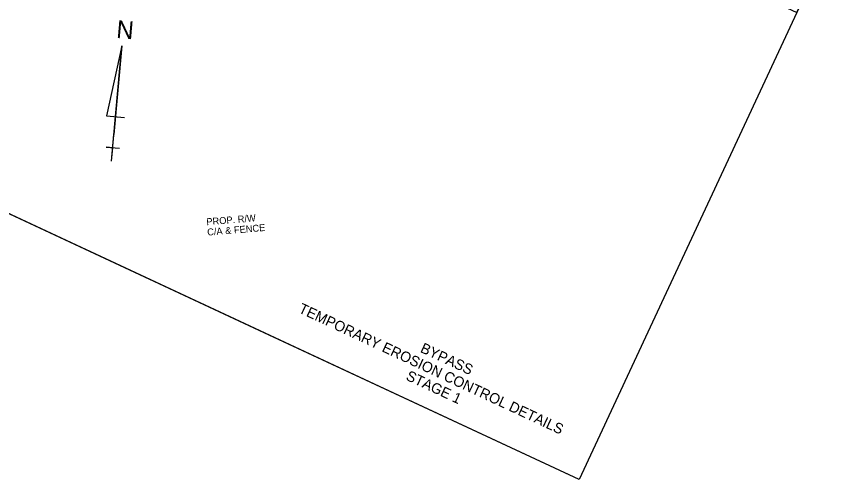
# Model space of a CAD drawing. Extents: x 980231 to 982096, y 1837566 to 1839185.
# Drawn here: x 981190 to 981897, y 1837566 to 1837967 of the extents above; entities that cross this region are included whole.
import ezdxf

# ---------------------------------------------------------------- set-up
doc = ezdxf.new("R2010")
doc.units = 0
for name, color, linetype in [('60', 7, 'Continuous'), ('63', 7, 'Continuous'), ('G-Border-Sheet', 7, 'Continuous'), ('R_Draft', 7, 'Continuous')]:
    doc.layers.add(name, color=color, linetype=linetype)

msp = doc.modelspace()

# ---------------------------------------------------------------- linework, layer by layer
at = {"layer": '63'}
for p, q in [((981281.06, 1837941.12), (981268.03, 1837880.49)), ((981272.34, 1837841.5), (981281.06, 1837941.12)), ((981281.06, 1837941.12), (981274.35, 1837864.49)), ((981268.03, 1837880.49), (981283.36, 1837879.15)), ((981272.34, 1837841.5), (981274.35, 1837864.49)), ((981273.35, 1837853), (981267.6, 1837853.5)), ((981267.6, 1837853.5), (981279.09, 1837852.49)), ((981272.34, 1837841.5), (981273.35, 1837853))]:
    msp.add_line(p, q, dxfattribs=at)
at = {"layer": 'G-Border-Sheet'}
for points in [[(981897.02, 1838038.3), (981676.77, 1837565.97), (981495.51, 1837650.49), (980230.88, 1838240.2), (980451.13, 1838712.53), (980461.01, 1838707.92), (980430.47, 1838642.44), (980815.65, 1838462.83), (980846.18, 1838528.31), (981586.46, 1838183.11), (981554.64, 1838114.87), (981865.2, 1837970.06), (981897.02, 1838038.3)], [(981897.02, 1838038.3), (981676.77, 1837565.97), (981495.51, 1837650.49), (980230.88, 1838240.2), (980451.13, 1838712.53), (980461.01, 1838707.92), (980430.47, 1838642.44), (980815.65, 1838462.83), (980846.18, 1838528.31), (981586.46, 1838183.11), (981554.64, 1838114.87), (981865.2, 1837970.06), (981897.02, 1838038.3)], [(981897.02, 1838038.3), (981676.77, 1837565.97), (981495.51, 1837650.49), (980230.88, 1838240.2), (980451.13, 1838712.53), (980461.01, 1838707.92), (980430.52, 1838642.55), (980815.7, 1838462.93), (980846.18, 1838528.31), (981586.46, 1838183.11), (981554.64, 1838114.87), (981865.2, 1837970.06), (981897.02, 1838038.3)], [(981897.02, 1838038.3), (981676.77, 1837565.97), (981495.51, 1837650.49), (980230.88, 1838240.2), (980450.96, 1838712.16), (980460.84, 1838707.56), (980430.52, 1838642.55), (980815.7, 1838462.93), (980846.18, 1838528.31), (981586.46, 1838183.11), (981554.64, 1838114.87), (981865.2, 1837970.06), (981897.02, 1838038.3)], [(981865.2, 1837970.06), (981676.77, 1837565.97), (981404.39, 1837692.98), (980230.88, 1838240.2), (980450.81, 1838711.85), (980460.69, 1838707.24), (980430.52, 1838642.55), (980815.7, 1838462.93), (980846.18, 1838528.31), (981586.46, 1838183.11), (981554.64, 1838114.87)]]:
    msp.add_lwpolyline(points, close=True, dxfattribs=at)

# ---------------------------------------------------------------- texts
at = {"layer": '60'}
for s, p in [('TEMPORARY EROSION CONTROL DETAILS', (981433.37, 1837710.79)), ('BYPASS', (981538.69, 1837676.58)), ('STAGE 1', (981526.25, 1837652.59))]:
    msp.add_text(s, height=9, rotation=335, dxfattribs=at).set_placement(p)
at = {"layer": '63'}
msp.add_text('N', height=15.38, rotation=355, dxfattribs=at).set_placement((981276, 1837948))
at = {"layer": 'R_Draft'}
for s, p in [('PROP. R/W', (981354.54, 1837785.94)), ('C/A & FENCE', (981355.27, 1837776.97))]:
    msp.add_text(s, height=6, rotation=4.63647, dxfattribs=at).set_placement(p)

doc.saveas('drawing.dxf')
